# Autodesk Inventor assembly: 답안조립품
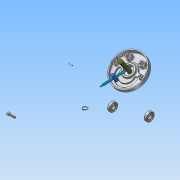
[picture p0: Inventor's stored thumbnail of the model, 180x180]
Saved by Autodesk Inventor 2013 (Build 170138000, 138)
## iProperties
Created: 2015-04
Part Number: 답안조립품
Document SubType Name: Assembly
Designer: Administrator
Author: Administrator
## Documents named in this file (10)
- C:\Users\Administrator\Desktop\450406V1047\답안조립품.iam
- C:\Users\Administrator\Desktop\450406V1047\본체.ipt
- C:\Users\Administrator\Desktop\450406V1047\M 10 x 35.ipt
- C:\Users\Administrator\Desktop\450406V1047\덮개.ipt
- C:\Users\Administrator\Desktop\450406V1047\멈춤링.ipt
- C:\Users\Administrator\Desktop\450406V1047\베어링62_22.ipt
- C:\Users\Administrator\Desktop\450406V1047\슬라이더.ipt
- C:\Users\Administrator\Desktop\450406V1047\슬라이더2.ipt
- C:\Users\Administrator\Desktop\450406V1047\축.ipt
- C:\Users\Administrator\Desktop\450406V1047\평행핀.ipt
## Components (1 placed, 1 different names)
1. M 10 x 35:1
